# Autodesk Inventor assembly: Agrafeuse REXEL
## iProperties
Author: Flavien MARTY
Shininess: 21.0
PropertySet Name: _Private Model Information
Created: 2001-10
Part Number: Agrafeuse REXEL
Document SubType Name: Assemblage
Designer: Flavien MARTY
Control State: 0
Master: False
Checked Out: False
PropertySet Name: Design Tracking Control
Density: 0.0
Volumn: 0.0
Area: 0.0
PropertySet Name: Model Information
